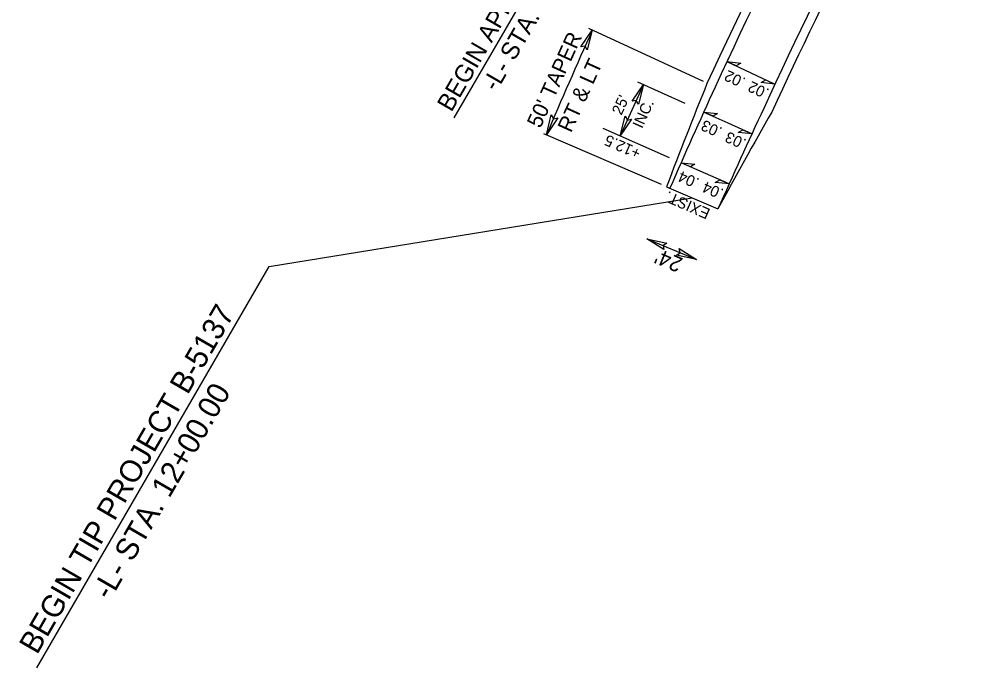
# Model space of a CAD drawing. Extents: x 1653308 to 1654073, y 597542 to 598622.
# Drawn here: x 1653308.2 to 1653741.9, y 597541.7 to 597835.4 of the extents above; entities that cross this region are included whole.
import ezdxf

# ---------------------------------------------------------------- set-up
doc = ezdxf.new("R2010")
doc.units = 0
for name, color, linetype in [('Prop Dimension', 7, 'Continuous'), ('Prop Dimension Text', 7, 'Continuous'), ('Prop EOT', 7, 'Continuous'), ('Prop Paved Shoulder', 7, 'Continuous'), ('Prop Superelevation  Arrow CELL', 7, 'Continuous'), ('Prop Superelevation Label', 7, 'Continuous'), ('Prop Terminator CELL', 7, 'Continuous')]:
    doc.layers.add(name, color=color, linetype=linetype)

msp = doc.modelspace()

# ---------------------------------------------------------------- linework, layer by layer
at = {"layer": 'Prop Dimension'}
for p, q in [((1653505.04, 597790.67), (1653575.7, 597912.69)), ((1653617.86, 597807.16), (1653565.89, 597831.06)), ((1653590.65, 597805.73), (1653580.09, 597782.49)), ((1653609.54, 597797.1), (1653588.15, 597806.79)), ((1653602.47, 597772.64), (1653572.41, 597785.87)), ((1653545.39, 597783.66), (1653598.6, 597760.59)), ((1653421.35, 597723.4), (1653612.74, 597754.46)), ((1653592.22, 597735.95), (1653614.58, 597726.55)), ((1653316.11, 597541.67), (1653421.35, 597723.4))]:
    msp.add_line(p, q, dxfattribs=at)
msp.add_arc((1655742.2, 596851.09), 2385, 155.75874, 156.99859, dxfattribs=at)
at = {"layer": 'Prop EOT'}
msp.add_line((1653601.11, 597759.5), (1653624.37, 597749.42), dxfattribs=at)
for centre, radius, start, end in [((1655696.35, 596851.16), 2282, 149.9451, 155.30659), ((1655696.35, 596851.16), 2258, 149.9451, 155.29325), ((1655696.35, 596851.16), 2282, 155.30659, 156.56208), ((1655690.53, 596838.14), 2258.2, 154.93139, 156.20023)]:
    msp.add_arc(centre, radius, start, end, dxfattribs=at)
at = {"layer": 'Prop Paved Shoulder'}
for centre, radius, start, end in [((1655696.35, 596851.16), 2286, 149.71581, 155.30659), ((1655696.35, 596851.16), 2254, 150.63058, 155.29325), ((1655773.04, 596935.6), 2322.95, 157.99003, 159.22626), ((1655615.09, 596674.2), 2262.54, 150.35591, 151.62588)]:
    msp.add_arc(centre, radius, start, end, dxfattribs=at)
at = {"layer": 'Prop Superelevation  Arrow CELL'}
for p, q in [((1653628.42, 597816.13), (1653639.29, 597811.06)), ((1653639.29, 597811.06), (1653650.17, 597805.98)), ((1653617.92, 597793.3), (1653628.85, 597788.35)), ((1653628.85, 597788.35), (1653639.77, 597783.39)), ((1653618.65, 597765.52), (1653607.67, 597770.35)), ((1653629.42, 597760.78), (1653618.65, 597765.52))]:
    msp.add_line(p, q, dxfattribs=at)
for points in [[(1653628.42, 597816.13), (1653634.7, 597815.41), (1653632.61, 597814.18)], [(1653650.17, 597805.98), (1653643.88, 597806.71), (1653645.98, 597807.94)], [(1653617.92, 597793.3), (1653624.21, 597792.64), (1653622.13, 597791.39)], [(1653639.77, 597783.39), (1653633.48, 597784.05), (1653635.56, 597785.3)], [(1653607.67, 597770.35), (1653613.96, 597769.77), (1653611.9, 597768.49)], [(1653629.42, 597760.78), (1653623.12, 597761.37), (1653625.18, 597762.64)]]:
    msp.add_lwpolyline(points, close=True, dxfattribs=at)
at = {"layer": 'Prop Superelevation Label'}
msp.add_line((1653644.94, 597794.7), (1653644.94, 597794.7), dxfattribs=at)
at = {"layer": 'Prop Terminator CELL'}
for points in [[(1653562.33, 597822.79), (1653567.49, 597830.32), (1653565.17, 597821.43), (1653564.2, 597823.14)], [(1653585.52, 597798.17), (1653590.65, 597805.73), (1653588.36, 597796.82), (1653587.38, 597798.53)], [(1653551.83, 597790.67), (1653546.82, 597783.04), (1653548.96, 597791.97), (1653549.97, 597790.28)], [(1653585.23, 597790.04), (1653580.09, 597782.49), (1653582.38, 597791.39), (1653583.36, 597789.68)], [(1653599.91, 597731.04), (1653592.22, 597735.95), (1653601.18, 597733.92), (1653599.5, 597732.89)], [(1653606.88, 597731.47), (1653614.58, 597726.55), (1653605.62, 597728.58), (1653607.3, 597729.61)]]:
    msp.add_lwpolyline(points, close=True, dxfattribs=at)

# ---------------------------------------------------------------- texts
at = {"layer": 'Prop Dimension Text'}
for s, height, rotation, p in [('BEGIN APPROACH SLAB', 8, 59.9255, (1653503.75, 597792.94)), ('-L- STA. 14+61.85', 8, 59.9255, (1653524.13, 597802.18)), ("50' TAPER", 7, 65.5658, (1653544, 597785.6)), ('RT & LT', 7, 65.5658, (1653557.87, 597783.58)), ("25'", 5, 65.5658, (1653580.67, 597791.54)), ('INC.', 5, 65.5658, (1653590.04, 597785.52)), ('+12.5', 5, 156.2466, (1653589.94, 597776.4)), ("24'", 7, 157.1931, (1653608.95, 597726.89)), ('BEGIN TIP PROJECT B-5137', 10, 59.9255, (1653316.27, 597547.28)), ('-L- STA. 12+00.00', 10, 59.9255, (1653349.27, 597571.85))]:
    msp.add_text(s, height=height, rotation=rotation, dxfattribs=at).set_placement(p)
at = {"layer": 'Prop Superelevation Label'}
for s, rotation, p in [('.02', 154.9846, (1653637.25, 597808.52)), ('.02', 154.9846, (1653647.94, 597803.53)), ('.03', 155.6156, (1653626.69, 597786.05)), ('.03', 155.6156, (1653637.59, 597780.77)), ('.04', 156.2466, (1653616.29, 597763.06)), ('.04', 156.2466, (1653627.3, 597758.22)), ('EXIST.', 156.3883, (1653621.27, 597749.19))]:
    msp.add_text(s, height=5, rotation=rotation, dxfattribs=at).set_placement(p)

doc.saveas('drawing.dxf')
